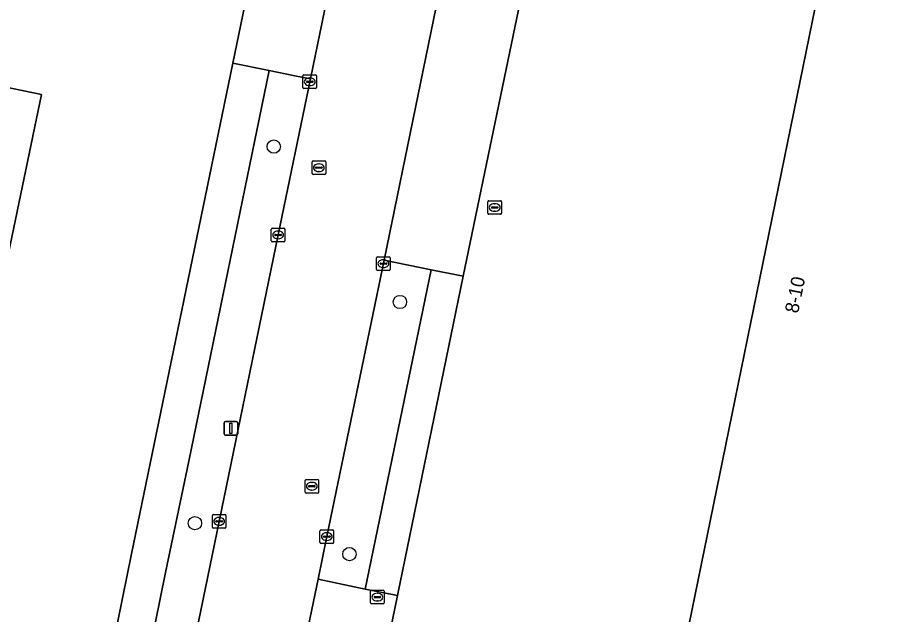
# Model space of a CAD drawing. Extents: x 157692 to 159674, y 381452 to 383291.
# Drawn here: x 158207.7 to 158272.6, y 382296.4 to 382340.2 of the extents above; entities that cross this region are included whole.
import ezdxf

# ---------------------------------------------------------------- set-up
doc = ezdxf.new("R2010")
doc.units = 0
for name, color, linetype in [('IMGEO_Berm_groen', 7, 'Continuous'), ('IMGEO_Boom', 7, 'Continuous'), ('IMGEO_Brandkraan', 7, 'Continuous'), ('IMGEO_Erf', 7, 'Continuous'), ('IMGEO_Kolk', 7, 'Continuous'), ('IMGEO_Lichtmast', 7, 'Continuous'), ('IMGEO_Pand', 7, 'Continuous'), ('IMGEO_Pand_nummerreeks', 7, 'Continuous'), ('IMGEO_Rijbaan_lokaal_gesloten', 7, 'Continuous'), ('IMGEO_Rioolput', 7, 'Continuous'), ('IMGEO_Voetpad_open', 7, 'Continuous')]:
    doc.layers.add(name, color=color, linetype=linetype)

msp = doc.modelspace()

# ---------------------------------------------------------------- linework, layer by layer
at = {"layer": 'IMGEO_Berm_groen'}
for points in [[(158226.818, 382324.222), (158229.188, 382335.673), (158228.057, 382335.904), (158226.164, 382336.29), (158220.253, 382307.626), (158218.559, 382299.459), (158214.782, 382280.855), (158212.696, 382270.641), (158215.933, 382271.278), (158216.232, 382272.751), (158218.642, 382284.562), (158222.488, 382303.203)], [(158238.047, 382321.666), (158234.593, 382322.37), (158230.388, 382302.082), (158229.747, 382298.967), (158233.197, 382298.231)]]:
    msp.add_lwpolyline(points, close=True, dxfattribs=at)
at = {"layer": 'IMGEO_Boom'}
for centre in [(158226.499, 382330.706), (158235.762, 382319.301), (158220.715, 382303.068), (158232.049, 382300.8)]:
    msp.add_circle(centre, 0.489, dxfattribs=at)
at = {"layer": 'IMGEO_Brandkraan'}
for p, q in [((158233.601, 382297.218), (158233.601, 382298.07)), ((158233.676, 382298.144), (158234.528, 382298.144)), ((158234.602, 382298.07), (158234.602, 382297.218)), ((158233.86, 382297.638), (158233.86, 382297.65)), ((158234.298, 382297.601), (158233.9, 382297.601)), ((158233.903, 382297.687), (158234.301, 382297.687)), ((158234.112, 382297.364), (158234.087, 382297.364)), ((158234.089, 382297.924), (158234.114, 382297.924)), ((158234.344, 382297.65), (158234.344, 382297.638)), ((158234.528, 382297.144), (158233.676, 382297.144))]:
    msp.add_line(p, q, dxfattribs=at)
for points in [[(158233.601, 382297.218), (158233.601, 382298.07)], [(158233.676, 382298.144), (158234.528, 382298.144)], [(158234.602, 382298.07), (158234.602, 382297.218)], [(158234.528, 382297.144), (158233.676, 382297.144)]]:
    msp.add_lwpolyline(points, dxfattribs=at)
for centre, radius, start, end in [((158233.678, 382298.068), 0.0765, 91.55205, 178.44795), ((158233.678, 382298.068), 0.0765, 91.55205, 178.44795), ((158234.526, 382298.068), 0.0765, 1.55205, 88.44795), ((158234.526, 382298.068), 0.0765, 1.55205, 88.44795), ((158233.9, 382297.647), 0.0403, 85.87752, 175.75265), ((158233.897, 382297.637), 0.0366, 178.93798, 274.71019), ((158234.301, 382297.644), 0.043, 264.86636, 352.45326), ((158234.305, 382297.649), 0.0386, 1.73085, 96.63898), ((158233.678, 382297.22), 0.0765, 181.55205, 268.44795), ((158233.678, 382297.22), 0.0765, 181.55205, 268.44795), ((158234.526, 382297.22), 0.0765, 271.55205, 358.44795), ((158234.526, 382297.22), 0.0765, 271.55205, 358.44795)]:
    msp.add_arc(centre, radius, start, end, dxfattribs=at)
for centre, major_axis, ratio, start_param, end_param in [((158234.088, 382297.644), (-0.387, 0.002), 0.722429, 4.712389, 7.853982), ((158234.113, 382297.644), (-0.39, 0.002), 0.717154, 1.570796, 4.712389)]:
    msp.add_ellipse(centre, major_axis=major_axis, ratio=ratio, start_param=start_param, end_param=end_param, dxfattribs=at)
at = {"layer": 'IMGEO_Erf'}
msp.add_lwpolyline([(158162.127, 382386.828), (158163.147, 382391.722), (158187.591, 382386.614), (158188.656, 382391.656), (158216.101, 382385.887), (158218.709, 382381.901), (158215.436, 382365.994), (158204.644, 382368.217), (158198.084, 382336.887), (158209.46, 382334.528), (158202.803, 382302.657), (158197.907, 382303.67), (158188.603, 382305.596), (158191.292, 382318.486), (158149.682, 382327.09)], close=True, dxfattribs=at)
for points in [[(158205.656, 382250), (158208.128, 382262.144), (158209.767, 382270.036), (158212.376, 382282.729), (158216.051, 382300.808), (158217.575, 382308.148), (158223.501, 382336.835), (158227.486, 382356.13)], [(158247.633, 382250), (158250.785, 382265.401), (158249.549, 382265.641), (158249.984, 382267.895), (158247.158, 382268.463), (158250.8, 382286.369), (158253.655, 382285.781), (158254.097, 382288.056), (158255.364, 382287.79), (158268.981, 382354.351)], [(158244.45, 382340.754), (158240.4, 382321.2), (158235.573, 382297.761), (158234.161, 382290.853), (158229.78, 382269.461), (158225.787, 382250), (158225.725, 382249.696), (158216.641, 382204.803), (158214.109, 382192.305), (158213.748, 382190.526), (158214.442, 382188.118), (158215.74, 382187.088), (158329.552, 382163.801), (158340.615, 382161.542)]]:
    msp.add_lwpolyline(points, dxfattribs=at)
at = {"layer": 'IMGEO_Kolk'}
for p, q in [((158228.642, 382335.038), (158228.642, 382335.89)), ((158228.717, 382335.964), (158229.569, 382335.964)), ((158229.13, 382335.744), (158229.155, 382335.744)), ((158229.643, 382335.89), (158229.643, 382335.038)), ((158229.569, 382334.964), (158228.717, 382334.964)), ((158228.901, 382335.458), (158228.901, 382335.47)), ((158229.339, 382335.421), (158228.941, 382335.421)), ((158228.944, 382335.507), (158229.342, 382335.507)), ((158229.153, 382335.184), (158229.128, 382335.184)), ((158229.385, 382335.47), (158229.385, 382335.458)), ((158226.32, 382323.796), (158226.32, 382324.648)), ((158226.395, 382324.722), (158227.247, 382324.722)), ((158227.321, 382324.648), (158227.321, 382323.796)), ((158226.579, 382324.216), (158226.579, 382324.228)), ((158227.017, 382324.179), (158226.619, 382324.179)), ((158226.622, 382324.265), (158227.02, 382324.265)), ((158226.831, 382323.942), (158226.806, 382323.942)), ((158226.808, 382324.502), (158226.833, 382324.502)), ((158227.063, 382324.228), (158227.063, 382324.216)), ((158227.247, 382323.722), (158226.395, 382323.722)), ((158234.12, 382322.614), (158234.972, 382322.614)), ((158234.045, 382321.688), (158234.045, 382322.54)), ((158234.304, 382322.108), (158234.304, 382322.12)), ((158234.742, 382322.071), (158234.344, 382322.071)), ((158234.347, 382322.157), (158234.745, 382322.157)), ((158234.533, 382322.394), (158234.558, 382322.394)), ((158234.788, 382322.12), (158234.788, 382322.108)), ((158235.046, 382322.54), (158235.046, 382321.688)), ((158234.972, 382321.614), (158234.12, 382321.614)), ((158234.556, 382321.834), (158234.531, 382321.834)), ((158221.99, 382302.777), (158221.99, 382303.629)), ((158222.065, 382303.703), (158222.917, 382303.703)), ((158222.249, 382303.197), (158222.249, 382303.209)), ((158222.687, 382303.16), (158222.289, 382303.16)), ((158222.292, 382303.246), (158222.69, 382303.246)), ((158222.478, 382303.483), (158222.503, 382303.483)), ((158222.733, 382303.209), (158222.733, 382303.197)), ((158222.991, 382303.629), (158222.991, 382302.777)), ((158222.917, 382302.703), (158222.065, 382302.703)), ((158222.501, 382302.923), (158222.476, 382302.923)), ((158229.892, 382301.656), (158229.892, 382302.508)), ((158229.967, 382302.582), (158230.819, 382302.582)), ((158230.893, 382302.508), (158230.893, 382301.656)), ((158230.151, 382302.076), (158230.151, 382302.088)), ((158230.589, 382302.039), (158230.191, 382302.039)), ((158230.194, 382302.125), (158230.592, 382302.125)), ((158230.38, 382302.362), (158230.405, 382302.362)), ((158230.635, 382302.088), (158230.635, 382302.076)), ((158230.819, 382301.582), (158229.967, 382301.582)), ((158230.403, 382301.802), (158230.378, 382301.802))]:
    msp.add_line(p, q, dxfattribs=at)
for points in [[(158228.642, 382335.038), (158228.642, 382335.89)], [(158228.717, 382335.964), (158229.569, 382335.964)], [(158229.643, 382335.89), (158229.643, 382335.038)], [(158229.569, 382334.964), (158228.717, 382334.964)], [(158226.32, 382323.796), (158226.32, 382324.648)], [(158226.395, 382324.722), (158227.247, 382324.722)], [(158227.321, 382324.648), (158227.321, 382323.796)], [(158227.247, 382323.722), (158226.395, 382323.722)], [(158234.12, 382322.614), (158234.972, 382322.614)], [(158234.045, 382321.688), (158234.045, 382322.54)], [(158235.046, 382322.54), (158235.046, 382321.688)], [(158234.972, 382321.614), (158234.12, 382321.614)], [(158221.99, 382302.777), (158221.99, 382303.629)], [(158222.065, 382303.703), (158222.917, 382303.703)], [(158222.991, 382303.629), (158222.991, 382302.777)], [(158222.917, 382302.703), (158222.065, 382302.703)], [(158229.892, 382301.656), (158229.892, 382302.508)], [(158229.967, 382302.582), (158230.819, 382302.582)], [(158230.893, 382302.508), (158230.893, 382301.656)], [(158230.819, 382301.582), (158229.967, 382301.582)]]:
    msp.add_lwpolyline(points, dxfattribs=at)
for centre, radius, start, end in [((158228.719, 382335.888), 0.0765, 91.55205, 178.44795), ((158228.719, 382335.888), 0.0765, 91.55205, 178.44795), ((158229.567, 382335.888), 0.0765, 1.55205, 88.44795), ((158229.567, 382335.888), 0.0765, 1.55205, 88.44795), ((158228.719, 382335.04), 0.0765, 181.55205, 268.44795), ((158228.719, 382335.04), 0.0765, 181.55205, 268.44795), ((158228.941, 382335.467), 0.0403, 85.87752, 175.75265), ((158228.938, 382335.457), 0.0366, 178.93798, 274.71019), ((158229.342, 382335.464), 0.043, 264.86636, 352.45326), ((158229.346, 382335.469), 0.0386, 1.73085, 96.63898), ((158229.567, 382335.04), 0.0765, 271.55205, 358.44795), ((158229.567, 382335.04), 0.0765, 271.55205, 358.44795), ((158226.397, 382324.646), 0.0765, 91.55205, 178.44795), ((158226.397, 382324.646), 0.0765, 91.55205, 178.44795), ((158227.245, 382324.646), 0.0765, 1.55205, 88.44795), ((158227.245, 382324.646), 0.0765, 1.55205, 88.44795), ((158226.619, 382324.225), 0.0403, 85.87752, 175.75265), ((158226.616, 382324.215), 0.0366, 178.93798, 274.71019), ((158227.02, 382324.222), 0.043, 264.86636, 352.45326), ((158227.024, 382324.227), 0.0386, 1.73085, 96.63898), ((158226.397, 382323.798), 0.0765, 181.55205, 268.44795), ((158226.397, 382323.798), 0.0765, 181.55205, 268.44795), ((158227.245, 382323.798), 0.0765, 271.55205, 358.44795), ((158227.245, 382323.798), 0.0765, 271.55205, 358.44795), ((158234.122, 382322.538), 0.0765, 91.55205, 178.44795), ((158234.122, 382322.538), 0.0765, 91.55205, 178.44795), ((158234.97, 382322.538), 0.0765, 1.55205, 88.44795), ((158234.97, 382322.538), 0.0765, 1.55205, 88.44795), ((158234.344, 382322.117), 0.0403, 85.87752, 175.75265), ((158234.341, 382322.107), 0.0366, 178.93798, 274.71019), ((158234.745, 382322.114), 0.043, 264.86636, 352.45326), ((158234.749, 382322.119), 0.0386, 1.73085, 96.63898), ((158234.122, 382321.69), 0.0765, 181.55205, 268.44795), ((158234.122, 382321.69), 0.0765, 181.55205, 268.44795), ((158234.97, 382321.69), 0.0765, 271.55205, 358.44795), ((158234.97, 382321.69), 0.0765, 271.55205, 358.44795), ((158222.067, 382303.627), 0.0765, 91.55205, 178.44795), ((158222.067, 382303.627), 0.0765, 91.55205, 178.44795), ((158222.289, 382303.206), 0.0403, 85.87752, 175.75265), ((158222.286, 382303.196), 0.0366, 178.93798, 274.71019), ((158222.69, 382303.203), 0.043, 264.86636, 352.45326), ((158222.694, 382303.208), 0.0386, 1.73085, 96.63898), ((158222.915, 382303.627), 0.0765, 1.55205, 88.44795), ((158222.915, 382303.627), 0.0765, 1.55205, 88.44795), ((158222.067, 382302.779), 0.0765, 181.55205, 268.44795), ((158222.067, 382302.779), 0.0765, 181.55205, 268.44795), ((158222.915, 382302.779), 0.0765, 271.55205, 358.44795), ((158222.915, 382302.779), 0.0765, 271.55205, 358.44795), ((158229.969, 382302.506), 0.0765, 91.55205, 178.44795), ((158229.969, 382302.506), 0.0765, 91.55205, 178.44795), ((158230.817, 382302.506), 0.0765, 1.55205, 88.44795), ((158230.817, 382302.506), 0.0765, 1.55205, 88.44795), ((158230.191, 382302.085), 0.0403, 85.87752, 175.75265), ((158230.188, 382302.075), 0.0366, 178.93798, 274.71019), ((158230.592, 382302.082), 0.043, 264.86636, 352.45326), ((158230.596, 382302.087), 0.0386, 1.73085, 96.63898), ((158229.969, 382301.658), 0.0765, 181.55205, 268.44795), ((158229.969, 382301.658), 0.0765, 181.55205, 268.44795), ((158230.817, 382301.658), 0.0765, 271.55205, 358.44795), ((158230.817, 382301.658), 0.0765, 271.55205, 358.44795)]:
    msp.add_arc(centre, radius, start, end, dxfattribs=at)
for centre, major_axis, ratio, start_param, end_param in [((158229.129, 382335.464), (-0.387, 0.002), 0.722429, 4.712389, 7.853982), ((158229.154, 382335.464), (-0.39, 0.002), 0.717154, 1.570796, 4.712389), ((158226.807, 382324.222), (-0.387, 0.002), 0.722429, 4.712389, 7.853982), ((158226.832, 382324.222), (-0.39, 0.002), 0.717154, 1.570796, 4.712389), ((158234.532, 382322.114), (-0.387, 0.002), 0.722429, 4.712389, 7.853982), ((158234.557, 382322.114), (-0.39, 0.002), 0.717154, 1.570796, 4.712389), ((158222.477, 382303.203), (-0.387, 0.002), 0.722429, 4.712389, 7.853982), ((158222.502, 382303.203), (-0.39, 0.002), 0.717154, 1.570796, 4.712389), ((158230.379, 382302.082), (-0.387, 0.002), 0.722429, 4.712389, 7.853982), ((158230.404, 382302.082), (-0.39, 0.002), 0.717154, 1.570796, 4.712389)]:
    msp.add_ellipse(centre, major_axis=major_axis, ratio=ratio, start_param=start_param, end_param=end_param, dxfattribs=at)
at = {"layer": 'IMGEO_Lichtmast'}
for p, q in [((158222.861, 382309.629), (158222.861, 382310.429)), ((158222.861, 382310.429), (158222.861, 382309.629)), ((158222.961, 382310.529), (158223.751, 382310.529)), ((158223.751, 382310.529), (158222.961, 382310.529)), ((158223.851, 382310.429), (158223.851, 382309.629)), ((158223.851, 382309.629), (158223.851, 382310.429)), ((158223.751, 382309.529), (158222.961, 382309.529)), ((158222.961, 382309.529), (158223.751, 382309.529))]:
    msp.add_line(p, q, dxfattribs=at)
msp.add_lwpolyline([(158223.281, 382310.404), (158223.431, 382310.404), (158223.431, 382309.654), (158223.281, 382309.654), (158223.281, 382310.404)], dxfattribs=at)
for centre, start, end in [((158222.961, 382310.429), 90, 180), ((158222.961, 382310.429), 90, 180), ((158223.751, 382310.429), 0, 90), ((158223.751, 382310.429), 360, 90), ((158222.961, 382309.629), 180, 270), ((158222.961, 382309.629), 180, 270), ((158223.751, 382309.629), 270, 0), ((158223.751, 382309.629), 270, 0)]:
    msp.add_arc(centre, 0.1, start, end, dxfattribs=at)
at = {"layer": 'IMGEO_Pand'}
msp.add_lwpolyline([(158162.127, 382386.828), (158149.682, 382327.09), (158191.292, 382318.486), (158188.603, 382305.596), (158197.907, 382303.67), (158202.803, 382302.657), (158209.46, 382334.528), (158198.084, 382336.887), (158204.644, 382368.217), (158215.436, 382365.994), (158218.709, 382381.901), (158216.101, 382385.887), (158188.656, 382391.656), (158187.591, 382386.614), (158163.147, 382391.722)], close=True, dxfattribs=at)
msp.add_lwpolyline([(158268.981, 382354.351), (158255.364, 382287.79), (158254.097, 382288.056), (158253.655, 382285.781), (158250.8, 382286.369), (158247.158, 382268.463), (158249.984, 382267.895), (158249.549, 382265.641), (158250.785, 382265.401), (158247.633, 382250)], dxfattribs=at)
at = {"layer": 'IMGEO_Rijbaan_lokaal_gesloten'}
for points in [[(158230.766, 382343.301), (158229.188, 382335.673), (158226.818, 382324.222), (158222.488, 382303.203), (158218.642, 382284.562), (158216.232, 382272.751), (158215.933, 382271.278), (158213.673, 382260.164), (158213.261, 382258.27), (158211.568, 382250), (158210.064, 382242.656), (158207.89, 382232.401), (158207.276, 382230.017), (158207.039, 382229.094), (158206.111, 382225.753), (158204.935, 382221.706), (158214.295, 382219.644)], [(158228.319, 382292.031), (158229.747, 382298.967), (158230.388, 382302.082), (158234.593, 382322.37), (158238.605, 382341.945)]]:
    msp.add_lwpolyline(points, dxfattribs=at)
at = {"layer": 'IMGEO_Rioolput'}
for p, q in [((158229.308, 382328.731), (158229.308, 382329.583)), ((158229.383, 382329.657), (158230.235, 382329.657)), ((158229.567, 382329.151), (158229.567, 382329.163)), ((158230.005, 382329.114), (158229.607, 382329.114)), ((158229.61, 382329.2), (158230.008, 382329.2)), ((158229.796, 382329.437), (158229.821, 382329.437)), ((158230.051, 382329.163), (158230.051, 382329.151)), ((158230.309, 382329.583), (158230.309, 382328.731)), ((158230.235, 382328.657), (158229.383, 382328.657)), ((158229.819, 382328.877), (158229.794, 382328.877)), ((158242.216, 382325.81), (158242.216, 382326.662)), ((158242.291, 382326.736), (158243.143, 382326.736)), ((158242.704, 382326.516), (158242.729, 382326.516)), ((158243.217, 382326.662), (158243.217, 382325.81)), ((158242.475, 382326.23), (158242.475, 382326.242)), ((158242.913, 382326.193), (158242.515, 382326.193)), ((158242.518, 382326.279), (158242.916, 382326.279)), ((158242.727, 382325.956), (158242.702, 382325.956)), ((158242.959, 382326.242), (158242.959, 382326.23)), ((158243.143, 382325.736), (158242.291, 382325.736)), ((158228.793, 382305.355), (158228.793, 382306.207)), ((158228.868, 382306.281), (158229.72, 382306.281)), ((158229.052, 382305.775), (158229.052, 382305.787)), ((158229.49, 382305.738), (158229.092, 382305.738)), ((158229.095, 382305.824), (158229.493, 382305.824)), ((158229.281, 382306.061), (158229.306, 382306.061)), ((158229.536, 382305.787), (158229.536, 382305.775)), ((158229.794, 382306.207), (158229.794, 382305.355)), ((158229.72, 382305.281), (158228.868, 382305.281)), ((158229.304, 382305.501), (158229.279, 382305.501))]:
    msp.add_line(p, q, dxfattribs=at)
for points in [[(158229.308, 382328.731), (158229.308, 382329.583)], [(158229.383, 382329.657), (158230.235, 382329.657)], [(158230.309, 382329.583), (158230.309, 382328.731)], [(158230.235, 382328.657), (158229.383, 382328.657)], [(158242.216, 382325.81), (158242.216, 382326.662)], [(158242.291, 382326.736), (158243.143, 382326.736)], [(158243.217, 382326.662), (158243.217, 382325.81)], [(158243.143, 382325.736), (158242.291, 382325.736)], [(158228.793, 382305.355), (158228.793, 382306.207)], [(158228.868, 382306.281), (158229.72, 382306.281)], [(158229.794, 382306.207), (158229.794, 382305.355)], [(158229.72, 382305.281), (158228.868, 382305.281)]]:
    msp.add_lwpolyline(points, dxfattribs=at)
for centre, radius, start, end in [((158229.385, 382329.581), 0.0765, 91.55205, 178.44795), ((158229.385, 382329.581), 0.0765, 91.55205, 178.44795), ((158229.607, 382329.16), 0.0403, 85.87752, 175.75265), ((158229.604, 382329.15), 0.0366, 178.93798, 274.71019), ((158230.008, 382329.157), 0.043, 264.86636, 352.45326), ((158230.012, 382329.162), 0.0386, 1.73085, 96.63898), ((158230.233, 382329.581), 0.0765, 1.55205, 88.44795), ((158230.233, 382329.581), 0.0765, 1.55205, 88.44795), ((158229.385, 382328.733), 0.0765, 181.55205, 268.44795), ((158229.385, 382328.733), 0.0765, 181.55205, 268.44795), ((158230.233, 382328.733), 0.0765, 271.55205, 358.44795), ((158230.233, 382328.733), 0.0765, 271.55205, 358.44795), ((158242.293, 382326.66), 0.0765, 91.55205, 178.44795), ((158242.293, 382326.66), 0.0765, 91.55205, 178.44795), ((158243.141, 382326.66), 0.0765, 1.55205, 88.44795), ((158243.141, 382326.66), 0.0765, 1.55205, 88.44795), ((158242.515, 382326.239), 0.0403, 85.87752, 175.75265), ((158242.512, 382326.229), 0.0366, 178.93798, 274.71019), ((158242.916, 382326.236), 0.043, 264.86636, 352.45326), ((158242.92, 382326.241), 0.0386, 1.73085, 96.63898), ((158242.293, 382325.812), 0.0765, 181.55205, 268.44795), ((158242.293, 382325.812), 0.0765, 181.55205, 268.44795), ((158243.141, 382325.812), 0.0765, 271.55205, 358.44795), ((158243.141, 382325.812), 0.0765, 271.55205, 358.44795), ((158228.87, 382306.205), 0.0765, 91.55205, 178.44795), ((158228.87, 382306.205), 0.0765, 91.55205, 178.44795), ((158229.092, 382305.784), 0.0403, 85.87752, 175.75265), ((158229.089, 382305.774), 0.0366, 178.93798, 274.71019), ((158229.493, 382305.781), 0.043, 264.86636, 352.45326), ((158229.497, 382305.786), 0.0386, 1.73085, 96.63898), ((158229.718, 382306.205), 0.0765, 1.55205, 88.44795), ((158229.718, 382306.205), 0.0765, 1.55205, 88.44795), ((158228.87, 382305.357), 0.0765, 181.55205, 268.44795), ((158228.87, 382305.357), 0.0765, 181.55205, 268.44795), ((158229.718, 382305.357), 0.0765, 271.55205, 358.44795), ((158229.718, 382305.357), 0.0765, 271.55205, 358.44795)]:
    msp.add_arc(centre, radius, start, end, dxfattribs=at)
for centre, major_axis, ratio, start_param, end_param in [((158229.795, 382329.157), (-0.387, 0.002), 0.722429, 4.712389, 7.853982), ((158229.82, 382329.157), (-0.39, 0.002), 0.717154, 1.570796, 4.712389), ((158242.703, 382326.236), (-0.387, 0.002), 0.722429, 4.712389, 7.853982), ((158242.728, 382326.236), (-0.39, 0.002), 0.717154, 1.570796, 4.712389), ((158229.28, 382305.781), (-0.387, 0.002), 0.722429, 4.712389, 7.853982), ((158229.305, 382305.781), (-0.39, 0.002), 0.717154, 1.570796, 4.712389)]:
    msp.add_ellipse(centre, major_axis=major_axis, ratio=ratio, start_param=start_param, end_param=end_param, dxfattribs=at)
at = {"layer": 'IMGEO_Voetpad_open'}
for points in [[(158230.148, 382355.519), (158227.486, 382356.13), (158223.501, 382336.835), (158226.164, 382336.29), (158228.057, 382335.904), (158229.188, 382335.673), (158230.766, 382343.301), (158233.162, 382354.852), (158231.999, 382355.109)], [(158238.047, 382321.666), (158240.4, 382321.2), (158244.45, 382340.754), (158242.085, 382341.256), (158238.605, 382341.945), (158234.593, 382322.37)], [(158209.767, 382270.036), (158212.696, 382270.641), (158214.782, 382280.855), (158218.559, 382299.459), (158220.253, 382307.626), (158226.164, 382336.29), (158223.501, 382336.835), (158217.575, 382308.148), (158216.051, 382300.808), (158212.376, 382282.729)], [(158233.197, 382298.231), (158235.573, 382297.761), (158240.4, 382321.2), (158238.047, 382321.666)], [(158231.802, 382291.336), (158234.161, 382290.853), (158235.573, 382297.761), (158233.197, 382298.231), (158229.747, 382298.967), (158228.319, 382292.031)]]:
    msp.add_lwpolyline(points, close=True, dxfattribs=at)

# ---------------------------------------------------------------- texts
at = {"layer": 'IMGEO_Pand_nummerreeks'}
msp.add_text('8-10', height=1, rotation=78.43792, dxfattribs=at).set_placement((158264.979, 382318.424))

doc.saveas('drawing.dxf')
